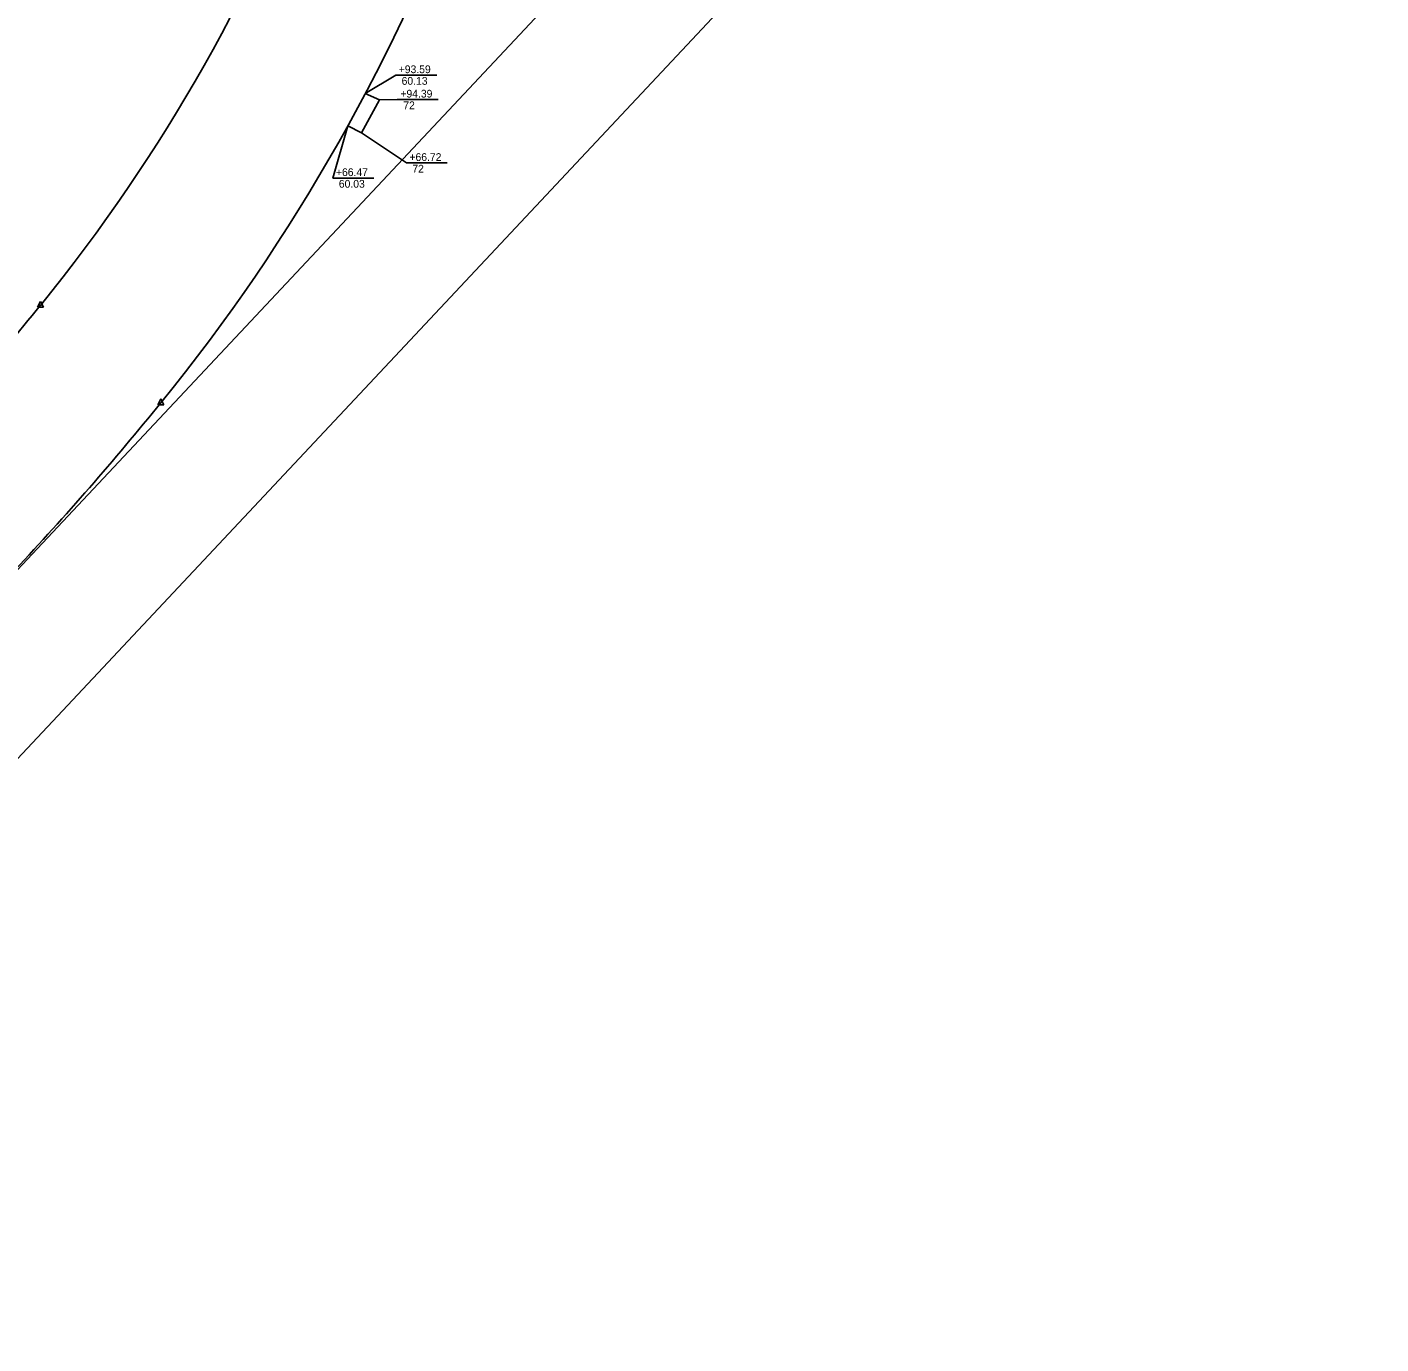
# Model space of a CAD drawing. Extents: x 979729 to 993523, y 1834148 to 1845433.
# Drawn here: x 992215 to 993263, y 1838663 to 1839683 of the extents above; entities that cross this region are included whole.
import ezdxf

# ---------------------------------------------------------------- set-up
doc = ezdxf.new("R2010")
doc.units = 0
for name, color, linetype in [('53', 7, 'Continuous'), ('R_Draft', 7, 'Continuous'), ('S_EXIST_ROW', 7, 'Continuous')]:
    doc.layers.add(name, color=color, linetype=linetype)

msp = doc.modelspace()

# ---------------------------------------------------------------- linework, layer by layer
at = {"layer": '53'}
for p, q in [((992487.6, 1839627), (992476.7, 1839631.8)), ((992473.9, 1839601.4), (992487.6, 1839627)), ((992473.9, 1839601.4), (992463.3, 1839606.9))]:
    msp.add_line(p, q, dxfattribs=at)
at = {"layer": 'R_Draft'}
for p, q in [((992506.3, 1839646.1), (992532, 1839646.1)), ((992507.5, 1839627.2), (992533.2, 1839627.2)), ((992514.5, 1839578.1), (992540.2, 1839578.1)), ((992457.7, 1839566.4), (992483.4, 1839566.4))]:
    msp.add_line(p, q, dxfattribs=at)
for points in [[(992476.7, 1839631.8), (992500.3, 1839646.1), (992506.3, 1839646.1)], [(992487.6, 1839627), (992501.5, 1839627.2), (992507.5, 1839627.2)], [(992463.3, 1839606.9), (992451.7, 1839566.4), (992457.7, 1839566.4)], [(992473.9, 1839601.4), (992508.5, 1839578.1), (992514.5, 1839578.1)]]:
    msp.add_lwpolyline(points, dxfattribs=at)
at = {"layer": 'S_EXIST_ROW'}
for p, q in [((990293.2, 1837222.2), (993190.2, 1840310.9)), ((990366.1, 1837153.8), (993263.1, 1840242.5)), ((992225.2, 1839470.8), (992223, 1839466.3)), ((992223, 1839466.3), (992227.5, 1839466.3)), ((992225.2, 1839470.8), (992227.5, 1839466.3)), ((992225.2, 1839467.8), (992225.2, 1839467.8)), ((992318.5, 1839395.3), (992316.2, 1839390.7)), ((992316.2, 1839390.7), (992320.7, 1839390.7)), ((992318.4, 1839392.2), (992318.4, 1839392.2)), ((992318.5, 1839395.3), (992320.7, 1839390.7))]:
    msp.add_line(p, q, dxfattribs=at)
for centre, radius in [((992225.2, 1839467.8), 0.0384), ((992225.2, 1839467.8), 0.0768), ((992318.4, 1839392.2), 0.0384), ((992318.4, 1839392.2), 0.0768)]:
    msp.add_circle(centre, radius, dxfattribs=at)
for centre, radius, start, end in [((991172.3, 1840321.7), 1355.7, 320.9582, 339.994), ((991172.3, 1840321.7), 1475.7, 320.9584, 339.9654), ((990464.6, 1840895.5), 2266.7, 316.839, 320.9613), ((990464.6, 1840895.5), 2386.7, 316.839, 320.9613)]:
    msp.add_arc(centre, radius, start, end, dxfattribs=at)

# ---------------------------------------------------------------- texts
at = {"layer": 'R_Draft'}
for s, p in [('+93.59', (992502.6, 1839647.6)), (' 60.13', (992502.6, 1839638.6)), ('+94.39', (992503.9, 1839628.7)), (' 72', (992503.9, 1839619.7)), ('+66.72', (992510.9, 1839579.6)), (' 72', (992510.9, 1839570.6)), ('+66.47', (992454, 1839567.9)), (' 60.03', (992454, 1839558.9))]:
    msp.add_text(s, height=6, rotation=360, dxfattribs=at).set_placement(p)

doc.saveas('drawing.dxf')
